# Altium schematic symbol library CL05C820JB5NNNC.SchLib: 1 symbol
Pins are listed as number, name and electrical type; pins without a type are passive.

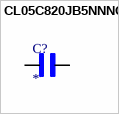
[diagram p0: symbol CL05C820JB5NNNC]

## CL05C820JB5NNNC
designator C?
MP: CL05C820JB5NNNC
footprint CAPC1005X55N
pins: 1, 2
